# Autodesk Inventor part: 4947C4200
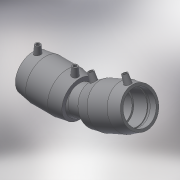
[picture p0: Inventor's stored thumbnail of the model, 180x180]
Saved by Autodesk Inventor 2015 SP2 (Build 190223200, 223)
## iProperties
Created: 2017-06
Part Number: 4947C4200
Material: Generic
Description: PLASSON ADJUSTABLE ELBOW 200
Document SubType Name: Modeling
Designer: KIM
Mass: 55.0731 g
Surface Area: 148.067 cm^2
Volume: 55.0731 cm^3
Density: 1 g/cm^3
Appearance: Default
Author: KIM
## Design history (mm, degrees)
derived "4947C4.ipt"
feature "Solid1::4947C4.ipt"
tag "TaggingFeature1"
body "Solid1"
other parameters: "d0" = 204.8, "d3" = 104, "d4" = 52, "d5" = 225, "d8" = 168 deg, "d10" = 41.6, "d11" = 13.86667, "d29" = 125, "d30" = 15, "d31" = 81.92, "d34" = 5 deg, "d41" = 4, "d42" = 14, "d43" = 0, "d49" = 24 deg, "d50" = 512, "d51" = 78 deg, "d52" = 90 deg, "d55" = 50.4, "d57" = 168 deg, "d58" = 10.08, "d60" = 60.1776, "d62" = 3, "d63" = 0, "L_" = 512, "L_1" = 104, "A_" = 125, "d_2" = 12, "L_0" = 148, "d54" = 100.8, "d59" = 200.59199
